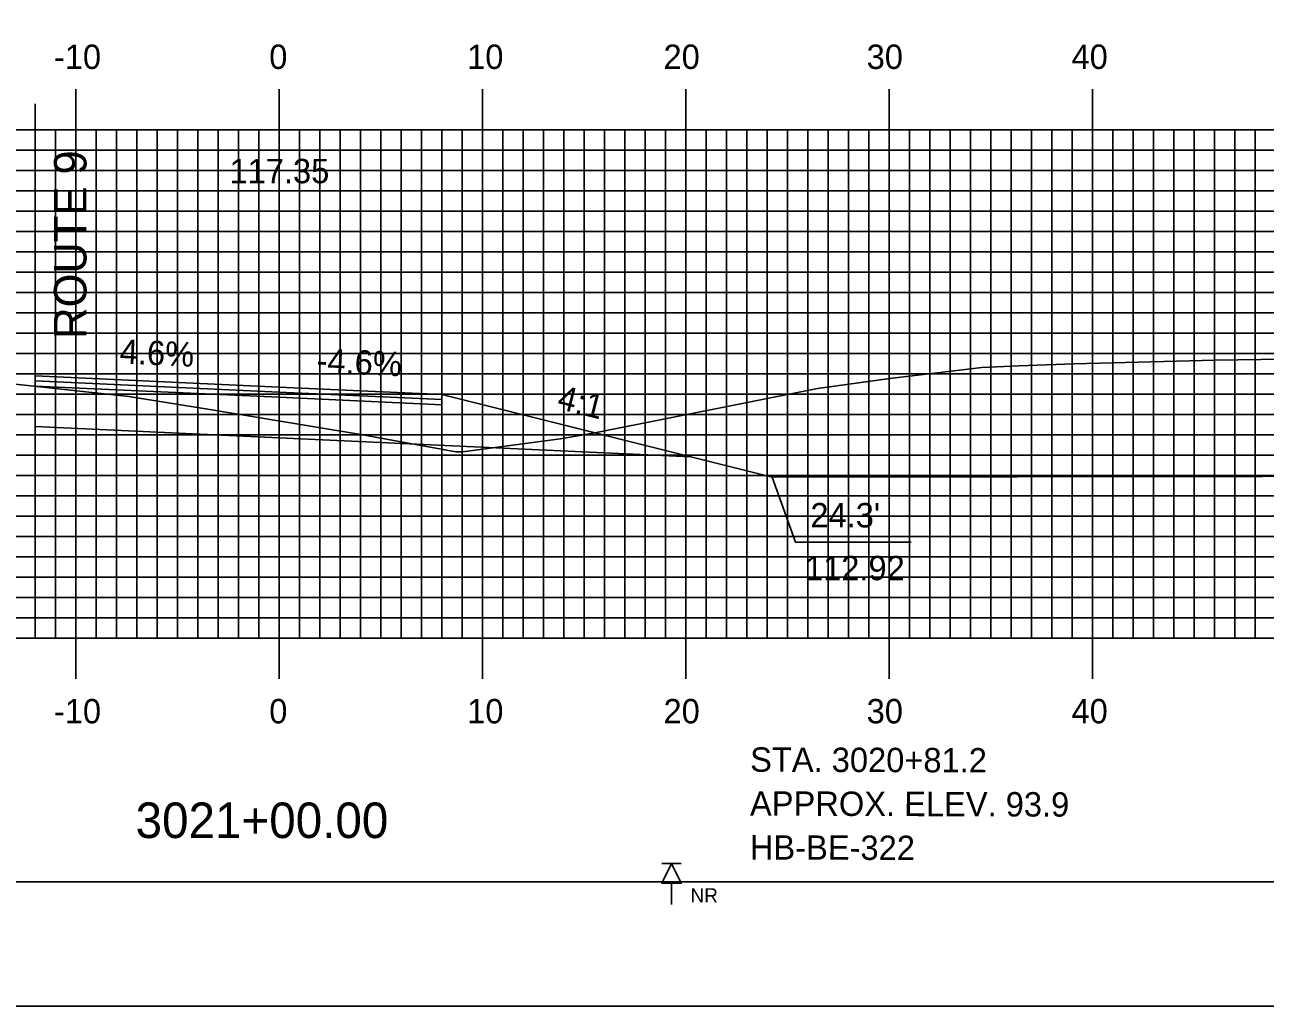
# Model space of a CAD drawing. Extents: x 1686373 to 1686716, y 461260 to 461480.
# Drawn here: x 1686526.3 to 1686587.3, y 461260 to 461308.2 of the extents above; entities that cross this region are included whole.
import ezdxf

# ---------------------------------------------------------------- set-up
doc = ezdxf.new("R2010")
doc.units = 0
for name, color, linetype in [('ANNOTATION', 7, 'Continuous'), ('BORDER', 7, 'Continuous'), ('BORING - NO REFUSAL', 7, 'Continuous'), ('D_Roadway_Centerline_Text', 7, 'Continuous'), ('D_Roadway_Edge_Shoulder', 7, 'Continuous'), ('D_Roadway_Edge_TW', 7, 'Continuous'), ('D_Roadway_Pavement', 7, 'Continuous'), ('D_Roadway_SlopeLines', 7, 'Continuous'), ('D_Roadway_SubGrade', 7, 'Continuous'), ('H_V ANNOTATION', 7, 'Continuous'), ('MAJOR', 7, 'Continuous'), ('MINOR', 7, 'Continuous'), ('PLOT BOUNDARY', 7, 'Continuous'), ('S_Roadway_Centerline', 7, 'Continuous')]:
    doc.layers.add(name, color=color, linetype=linetype)

msp = doc.modelspace()

# ---------------------------------------------------------------- linework, layer by layer
at = {"layer": 'ANNOTATION'}
msp.add_lwpolyline([(1686569.857, 461282.788), (1686564.165, 461282.788), (1686563.024, 461285.988)], dxfattribs=at)
at = {"layer": 'BORDER'}
msp.add_lwpolyline([(1686389.169, 461266.072), (1686709.169, 461266.072), (1686709.169, 461476.072), (1686389.169, 461476.072)], close=True, dxfattribs=at)
at = {"layer": 'BORING - NO REFUSAL'}
for p, q in [((1686558.549, 461266.972), (1686557.589, 461266.972)), ((1686558.069, 461266.013), (1686558.069, 461264.954))]:
    msp.add_line(p, q, dxfattribs=at)
msp.add_lwpolyline([(1686558.069, 461266.972), (1686558.549, 461266.013), (1686557.589, 461266.013)], close=True, dxfattribs=at)
at = {"layer": 'D_Roadway_Edge_Shoulder'}
for points in [[(1686538.769, 461290.42), (1686546.769, 461290.052), (1686546.769, 461289.802), (1686538.769, 461290.17)], [(1686538.769, 461290.42), (1686546.769, 461290.052), (1686546.769, 461289.802), (1686538.769, 461290.17)], [(1686538.769, 461290.42), (1686546.769, 461290.052), (1686546.769, 461289.802), (1686538.769, 461290.17)], [(1686538.769, 461290.17), (1686546.769, 461289.802), (1686546.769, 461289.552), (1686538.769, 461289.92)]]:
    msp.add_lwpolyline(points, close=True, dxfattribs=at)
at = {"layer": 'D_Roadway_Edge_TW'}
for points in [[(1686526.769, 461290.972), (1686526.769, 461290.722)], [(1686538.769, 461290.17), (1686538.769, 461290.42)]]:
    msp.add_lwpolyline(points, dxfattribs=at)
msp.add_lwpolyline([(1686526.769, 461290.969), (1686538.769, 461290.42), (1686538.769, 461290.17), (1686526.769, 461290.722)], close=True, dxfattribs=at)
at = {"layer": 'D_Roadway_Pavement'}
for points in [[(1686526.769, 461290.722), (1686526.769, 461290.472)], [(1686538.769, 461290.17), (1686538.769, 461289.92)], [(1686538.769, 461290.17), (1686538.769, 461289.92)], [(1686538.769, 461290.17), (1686538.769, 461289.92)], [(1686538.769, 461290.17), (1686538.769, 461289.92)], [(1686538.769, 461290.17), (1686538.769, 461289.92)], [(1686538.769, 461290.17), (1686538.769, 461289.92)], [(1686538.769, 461289.92), (1686538.769, 461290.17)], [(1686538.769, 461290.17), (1686538.769, 461289.92)]]:
    msp.add_lwpolyline(points, dxfattribs=at)
at = {"layer": 'D_Roadway_SlopeLines'}
for points in [[(1686546.769, 461290.052), (1686563.024, 461285.988)], [(1686546.769, 461290.052), (1686563.024, 461285.988)], [(1686546.769, 461290.052), (1686563.024, 461285.988)], [(1686546.769, 461290.052), (1686563.024, 461285.988)], [(1686563.024, 461285.988), (1686647.42, 461286.094)], [(1686563.024, 461285.988), (1686647.42, 461286.094)], [(1686563.024, 461285.988), (1686647.42, 461286.094)], [(1686563.024, 461285.988), (1686647.42, 461286.094)]]:
    msp.add_lwpolyline(points, dxfattribs=at)
at = {"layer": 'D_Roadway_SubGrade'}
msp.add_line((1686526.769, 461304.351), (1686526.769, 461288.472), dxfattribs=at)
msp.add_lwpolyline([(1686526.769, 461290.472), (1686526.769, 461288.472)], dxfattribs=at)
msp.add_lwpolyline([(1686526.769, 461290.472), (1686526.769, 461288.472)], dxfattribs=at)
for points in [[(1686526.769, 461290.472), (1686538.769, 461289.92), (1686538.769, 461287.92), (1686526.769, 461288.472)], [(1686526.769, 461290.472), (1686538.769, 461289.92), (1686538.769, 461287.92), (1686526.769, 461288.472)], [(1686526.769, 461290.472), (1686538.769, 461289.92), (1686538.769, 461287.92), (1686526.769, 461288.472)], [(1686538.769, 461287.92), (1686559.024, 461286.988), (1686546.769, 461290.052), (1686546.769, 461289.802), (1686538.769, 461290.17), (1686538.769, 461289.92)], [(1686538.769, 461289.92), (1686538.769, 461290.17), (1686546.769, 461289.802), (1686546.769, 461290.052), (1686559.024, 461286.988), (1686538.769, 461287.92)], [(1686538.769, 461289.92), (1686538.769, 461290.17), (1686546.769, 461289.802), (1686546.769, 461290.052), (1686559.024, 461286.988), (1686538.769, 461287.92)], [(1686538.769, 461287.92), (1686559.024, 461286.988), (1686546.769, 461290.052), (1686546.769, 461289.802), (1686538.769, 461290.17), (1686538.769, 461289.92)]]:
    msp.add_lwpolyline(points, close=True, dxfattribs=at)
at = {"layer": 'MAJOR'}
for p, q in [((1686528.769, 461305.076), (1686528.769, 461303.072)), ((1686538.769, 461305.076), (1686538.769, 461303.072)), ((1686548.769, 461305.076), (1686548.769, 461303.072)), ((1686558.769, 461305.076), (1686558.769, 461303.072)), ((1686568.769, 461305.076), (1686568.769, 461303.072)), ((1686578.769, 461305.076), (1686578.769, 461303.072)), ((1686398.769, 461303.072), (1686678.769, 461303.072)), ((1686398.769, 461303.072), (1686678.769, 461303.072)), ((1686528.769, 461278.072), (1686528.769, 461303.072)), ((1686538.769, 461278.072), (1686538.769, 461303.072)), ((1686548.769, 461278.072), (1686548.769, 461303.072)), ((1686558.769, 461278.072), (1686558.769, 461303.072)), ((1686568.769, 461278.072), (1686568.769, 461303.072)), ((1686578.769, 461278.072), (1686578.769, 461303.072)), ((1686398.769, 461298.072), (1686678.769, 461298.072)), ((1686398.769, 461293.072), (1686678.769, 461293.072)), ((1686398.769, 461288.072), (1686678.769, 461288.072)), ((1686398.769, 461283.072), (1686678.769, 461283.072)), ((1686398.769, 461278.072), (1686678.769, 461278.072)), ((1686398.769, 461278.072), (1686678.769, 461278.072)), ((1686528.769, 461276.068), (1686528.769, 461278.072)), ((1686538.769, 461276.068), (1686538.769, 461278.072)), ((1686548.769, 461276.068), (1686548.769, 461278.072)), ((1686558.769, 461276.068), (1686558.769, 461278.072)), ((1686568.769, 461276.068), (1686568.769, 461278.072)), ((1686578.769, 461276.068), (1686578.769, 461278.072))]:
    msp.add_line(p, q, dxfattribs=at)
at = {"layer": 'MINOR'}
for p, q in [((1686526.769, 461278.072), (1686526.769, 461303.072)), ((1686527.769, 461278.072), (1686527.769, 461303.072)), ((1686529.769, 461278.072), (1686529.769, 461303.072)), ((1686530.769, 461278.072), (1686530.769, 461303.072)), ((1686531.769, 461278.072), (1686531.769, 461303.072)), ((1686532.769, 461278.072), (1686532.769, 461303.072)), ((1686533.769, 461278.072), (1686533.769, 461303.072)), ((1686534.769, 461278.072), (1686534.769, 461303.072)), ((1686535.769, 461278.072), (1686535.769, 461303.072)), ((1686536.769, 461278.072), (1686536.769, 461303.072)), ((1686537.769, 461278.072), (1686537.769, 461303.072)), ((1686539.769, 461278.072), (1686539.769, 461303.072)), ((1686540.769, 461278.072), (1686540.769, 461303.072)), ((1686541.769, 461278.072), (1686541.769, 461303.072)), ((1686542.769, 461278.072), (1686542.769, 461303.072)), ((1686543.769, 461278.072), (1686543.769, 461303.072)), ((1686544.769, 461278.072), (1686544.769, 461303.072)), ((1686545.769, 461278.072), (1686545.769, 461303.072)), ((1686546.769, 461278.072), (1686546.769, 461303.072)), ((1686547.769, 461278.072), (1686547.769, 461303.072)), ((1686549.769, 461278.072), (1686549.769, 461303.072)), ((1686550.769, 461278.072), (1686550.769, 461303.072)), ((1686551.769, 461278.072), (1686551.769, 461303.072)), ((1686552.769, 461278.072), (1686552.769, 461303.072)), ((1686553.769, 461278.072), (1686553.769, 461303.072)), ((1686554.769, 461278.072), (1686554.769, 461303.072)), ((1686555.769, 461278.072), (1686555.769, 461303.072)), ((1686556.769, 461278.072), (1686556.769, 461303.072)), ((1686557.769, 461278.072), (1686557.769, 461303.072)), ((1686559.769, 461278.072), (1686559.769, 461303.072)), ((1686560.769, 461278.072), (1686560.769, 461303.072)), ((1686561.769, 461278.072), (1686561.769, 461303.072)), ((1686562.769, 461278.072), (1686562.769, 461303.072)), ((1686563.769, 461278.072), (1686563.769, 461303.072)), ((1686564.769, 461278.072), (1686564.769, 461303.072)), ((1686565.769, 461278.072), (1686565.769, 461303.072)), ((1686566.769, 461278.072), (1686566.769, 461303.072)), ((1686567.769, 461278.072), (1686567.769, 461303.072)), ((1686569.769, 461278.072), (1686569.769, 461303.072)), ((1686570.769, 461278.072), (1686570.769, 461303.072)), ((1686571.769, 461278.072), (1686571.769, 461303.072)), ((1686572.769, 461278.072), (1686572.769, 461303.072)), ((1686573.769, 461278.072), (1686573.769, 461303.072)), ((1686574.769, 461278.072), (1686574.769, 461303.072)), ((1686575.769, 461278.072), (1686575.769, 461303.072)), ((1686576.769, 461278.072), (1686576.769, 461303.072)), ((1686577.769, 461278.072), (1686577.769, 461303.072)), ((1686579.769, 461278.072), (1686579.769, 461303.072)), ((1686580.769, 461278.072), (1686580.769, 461303.072)), ((1686581.769, 461278.072), (1686581.769, 461303.072)), ((1686582.769, 461278.072), (1686582.769, 461303.072)), ((1686583.769, 461278.072), (1686583.769, 461303.072)), ((1686584.769, 461278.072), (1686584.769, 461303.072)), ((1686585.769, 461278.072), (1686585.769, 461303.072)), ((1686586.769, 461278.072), (1686586.769, 461303.072)), ((1686398.769, 461302.072), (1686678.769, 461302.072)), ((1686398.769, 461301.072), (1686678.769, 461301.072)), ((1686398.769, 461300.072), (1686678.769, 461300.072)), ((1686398.769, 461299.072), (1686678.769, 461299.072)), ((1686398.769, 461297.072), (1686678.769, 461297.072)), ((1686398.769, 461296.072), (1686678.769, 461296.072)), ((1686398.769, 461295.072), (1686678.769, 461295.072)), ((1686398.769, 461294.072), (1686678.769, 461294.072)), ((1686398.769, 461292.072), (1686678.769, 461292.072)), ((1686398.769, 461291.072), (1686678.769, 461291.072)), ((1686398.769, 461290.072), (1686678.769, 461290.072)), ((1686398.769, 461289.072), (1686678.769, 461289.072)), ((1686398.769, 461287.072), (1686678.769, 461287.072)), ((1686398.769, 461286.072), (1686678.769, 461286.072)), ((1686398.769, 461285.072), (1686678.769, 461285.072)), ((1686398.769, 461284.072), (1686678.769, 461284.072)), ((1686398.769, 461282.072), (1686678.769, 461282.072)), ((1686398.769, 461281.072), (1686678.769, 461281.072)), ((1686398.769, 461280.072), (1686678.769, 461280.072)), ((1686398.769, 461279.072), (1686678.769, 461279.072))]:
    msp.add_line(p, q, dxfattribs=at)
at = {"layer": 'PLOT BOUNDARY'}
msp.add_lwpolyline([(1686372.982, 461259.954), (1686712.982, 461259.954), (1686712.982, 461479.954), (1686372.982, 461479.954)], close=True, dxfattribs=at)
at = {"layer": 'S_Roadway_Centerline'}
msp.add_lwpolyline([(1686520.51, 461291.141), (1686531.377, 461289.951), (1686535.372, 461289.311), (1686542.793, 461288.079), (1686547.464, 461287.23), (1686547.805, 461287.232), (1686552.599, 461287.868), (1686552.989, 461287.94), (1686554.307, 461288.171), (1686565.248, 461290.347), (1686568.81, 461290.842), (1686573.324, 461291.375), (1686575.145, 461291.461), (1686577.869, 461291.567), (1686584.784, 461291.736), (1686589.323, 461291.802)], dxfattribs=at)

# ---------------------------------------------------------------- texts
at = {"layer": 'ANNOTATION'}
for s, height, rotation, p in [('ROUTE 9', 1.6, 90, (1686529.3, 461292.795)), ('4.6%', 1.2, 357.36625, (1686530.915, 461291.583)), ('-4.6%', 1.2, 357.36625, (1686540.594, 461291.138)), ('4:1', 1.2, 345.96376, (1686552.39, 461289.367))]:
    msp.add_text(s, height=height, rotation=rotation, dxfattribs=at).set_placement(p)
for s, p in [("24.3' ", (1686564.9, 461283.514)), ('112.92', (1686564.633, 461280.914))]:
    msp.add_text(s, height=1.2, dxfattribs=at).set_placement(p)
at = {"layer": 'BORING - NO REFUSAL'}
for s, p in [('STA. 3020+81.2', (1686561.936, 461271.492)), ('APPROX. ELEV. 93.9', (1686561.929, 461269.332)), ('HB-BE-322', (1686561.922, 461267.172))]:
    msp.add_text(s, height=1.2, rotation=359.81416, dxfattribs=at).set_placement(p)
msp.add_text('NR', height=0.6998, dxfattribs=at).set_placement((1686559.001, 461265.057))
at = {"layer": 'D_Roadway_Centerline_Text'}
msp.add_text('117.35', height=1.2, dxfattribs=at).set_placement((1686536.334, 461300.45))
at = {"layer": 'H_V ANNOTATION'}
for s, height, p in [('-10', 1.2, (1686527.698, 461306.072)), ('0', 1.2, (1686538.287, 461306.072)), ('10', 1.2, (1686548.019, 461306.072)), ('20', 1.2, (1686557.677, 461306.072)), ('30', 1.2, (1686567.666, 461306.072)), ('40', 1.2, (1686577.741, 461306.072)), ('-10', 1.2, (1686527.698, 461273.872)), ('0', 1.2, (1686538.287, 461273.872)), ('10', 1.2, (1686548.019, 461273.872)), ('20', 1.2, (1686557.677, 461273.872)), ('30', 1.2, (1686567.666, 461273.872)), ('40', 1.2, (1686577.741, 461273.872)), ('3021+00.00', 1.75, (1686531.715, 461268.228))]:
    msp.add_text(s, height=height, dxfattribs=at).set_placement(p)

doc.saveas('drawing.dxf')
